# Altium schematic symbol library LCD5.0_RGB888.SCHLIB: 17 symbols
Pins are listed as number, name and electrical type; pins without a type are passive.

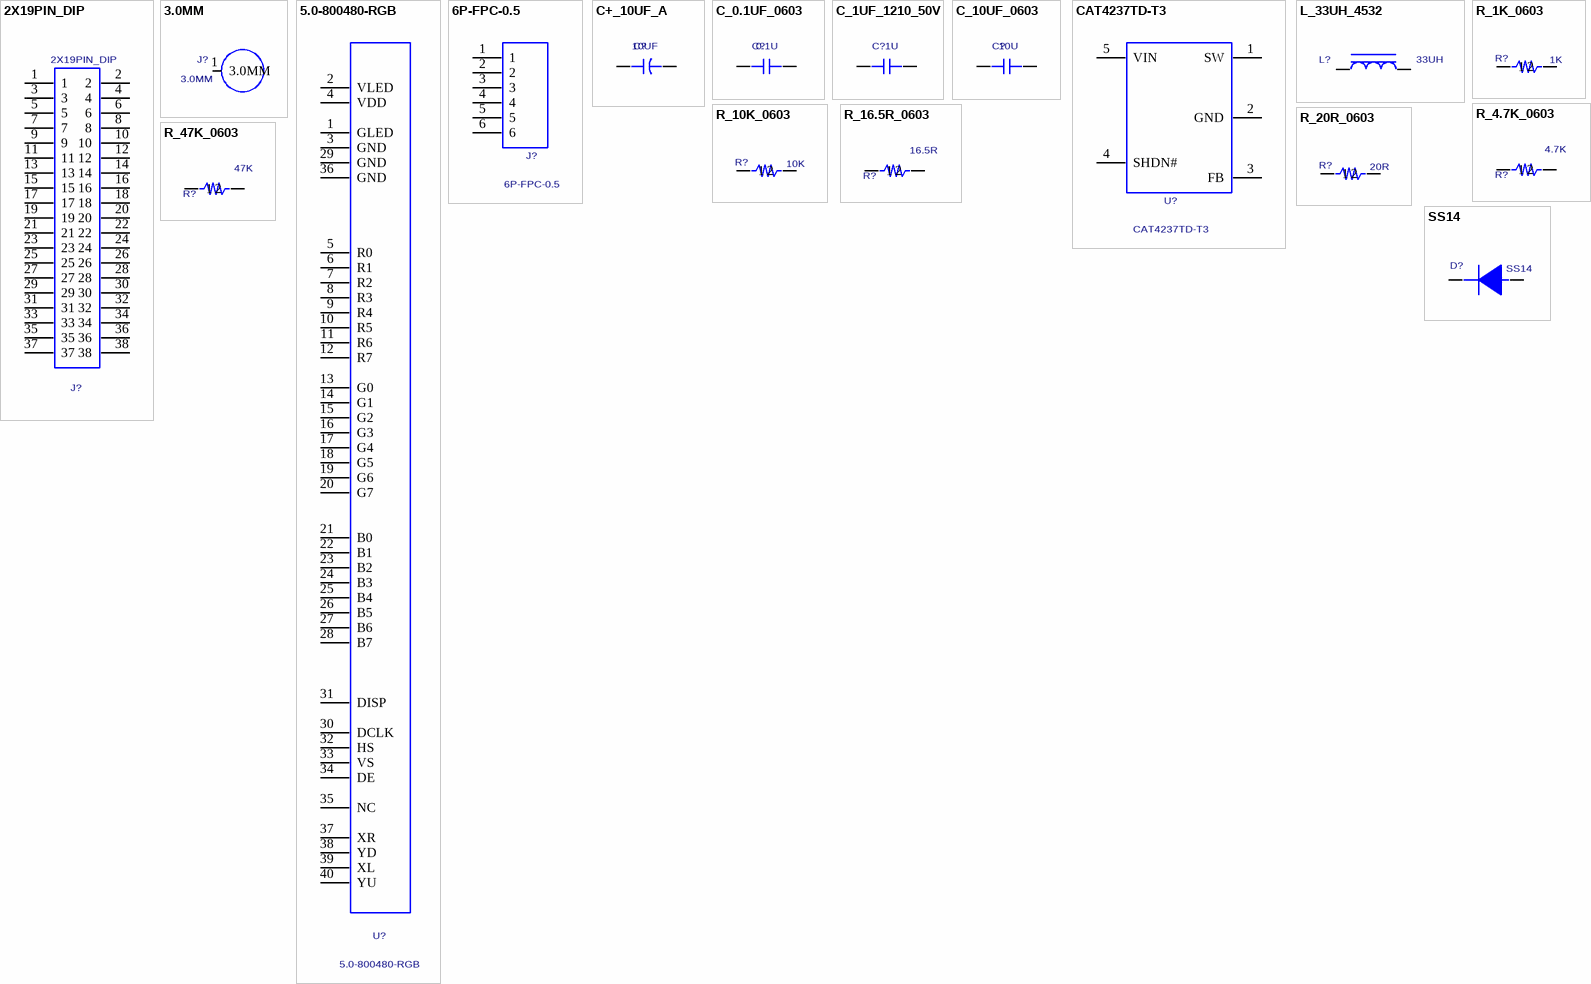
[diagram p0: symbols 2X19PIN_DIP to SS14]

## 2X19PIN_DIP
designator J?
PCB DECAL: 2X19X2.54MM
footprint 2X19X2.54MM
pins: 1, 2, 3, 4, 5, 6, 7, 8, 9, 10, 11, 12, 13, 14, 15, 16, 17, 18, 19, 20, 21, 22, 23, 24, 25, 26, 27, 28, 29, 30, 31, 32, 33, 34, 35, 36, 37, 38

## 3.0MM
designator J?
footprint 3.0MM
pins: 1 3.0MM

## 5.0-800480-RGB
designator U?
PCB DECAL: TFT5.0; Value: FPC-0.5MM-40P
footprint TFT5.0
pins: 1 GLED, 2 VLED, 3 GND, 4 VDD, 5 R0, 6 R1, 7 R2, 8 R3, 9 R4, 10 R5, 11 R6, 12 R7, 13 G0, 14 G1, 15 G2, 16 G3, 17 G4, 18 G5, 19 G6, 20 G7, 21 B0, 22 B1, 23 B2, 24 B3, 25 B4, 26 B5, 27 B6, 28 B7, 29 GND, 30 DCLK, 31 DISP, 32 HS, 33 VS, 34 DE, 35 NC, 36 GND, 37 XR, 38 YD, 39 XL, 40 YU

## 6P-FPC-0.5
designator J?
Value: FPC-0.5MM-6P
footprint 6P-FPC-0.5
pins: 1, 2, 3, 4, 5, 6

## C+_10UF_A
designator C?  value 10UF  (hidden comment: C+_10UF_A)
PCB DECAL: AVX_A_3216-18
footprint AVX_A_3216-18
pins: 1 +, 2 -

## C_0.1UF_0603
designator C?  value 0.1U  (hidden comment: C_0.1UF_0603)
PCB DECAL: C_0603
footprint C_0603
pins: 1, 2

## C_1UF_1210_50V
designator C?  value 1U  (hidden comment: C_1UF_1210_50V)
PCB DECAL: 1210
footprint 1210
pins: 1, 2

## C_10UF_0603
designator C?  value 10U  (hidden comment: C_10UF_0603)
PCB DECAL: C_0603
footprint C_0603
pins: 1, 2

## CAT4237TD-T3
designator U?
PCB DECAL: SOT-23-5
footprint SOT-23-5
pins: 1 SW, 2 GND, 3 FB, 4 SHDN#, 5 VIN

## L_33UH_4532
designator L?  value 33UH  (hidden comment: L_33UH_4532)
PCB DECAL: GDCD4532
footprint GDCD4532
pins: 1, 2

## R_1K_0603
designator R?  value 1K  (hidden comment: R_1K_0603)
PCB DECAL: R_0603
footprint R_0603
pins: 1, 2

## R_4.7K_0603
designator R?  value 4.7K  (hidden comment: R_4.7K_0603)
PCB DECAL: R_0603
footprint R_0603
pins: 1, 2

## R_10K_0603
designator R?  value 10K  (hidden comment: R_10K_0603)
PCB DECAL: R_0603
footprint R_0603
pins: 1, 2

## R_16.5R_0603
designator R?  value 16.5R  (hidden comment: R_16.5R_0603)
PCB DECAL: R_0603
footprint R_0603
pins: 1, 2

## R_20R_0603
designator R?  value 20R  (hidden comment: R_20R_0603)
PCB DECAL: R_0603
footprint R_0603
pins: 1, 2

## R_47K_0603
designator R?  value 47K  (hidden comment: R_47K_0603)
PCB DECAL: R_0603
footprint R_0603
pins: 1, 2

## SS14
designator D?
PCB DECAL: SS24_1206
footprint SS24_1206
pins: 1 +, 2 -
